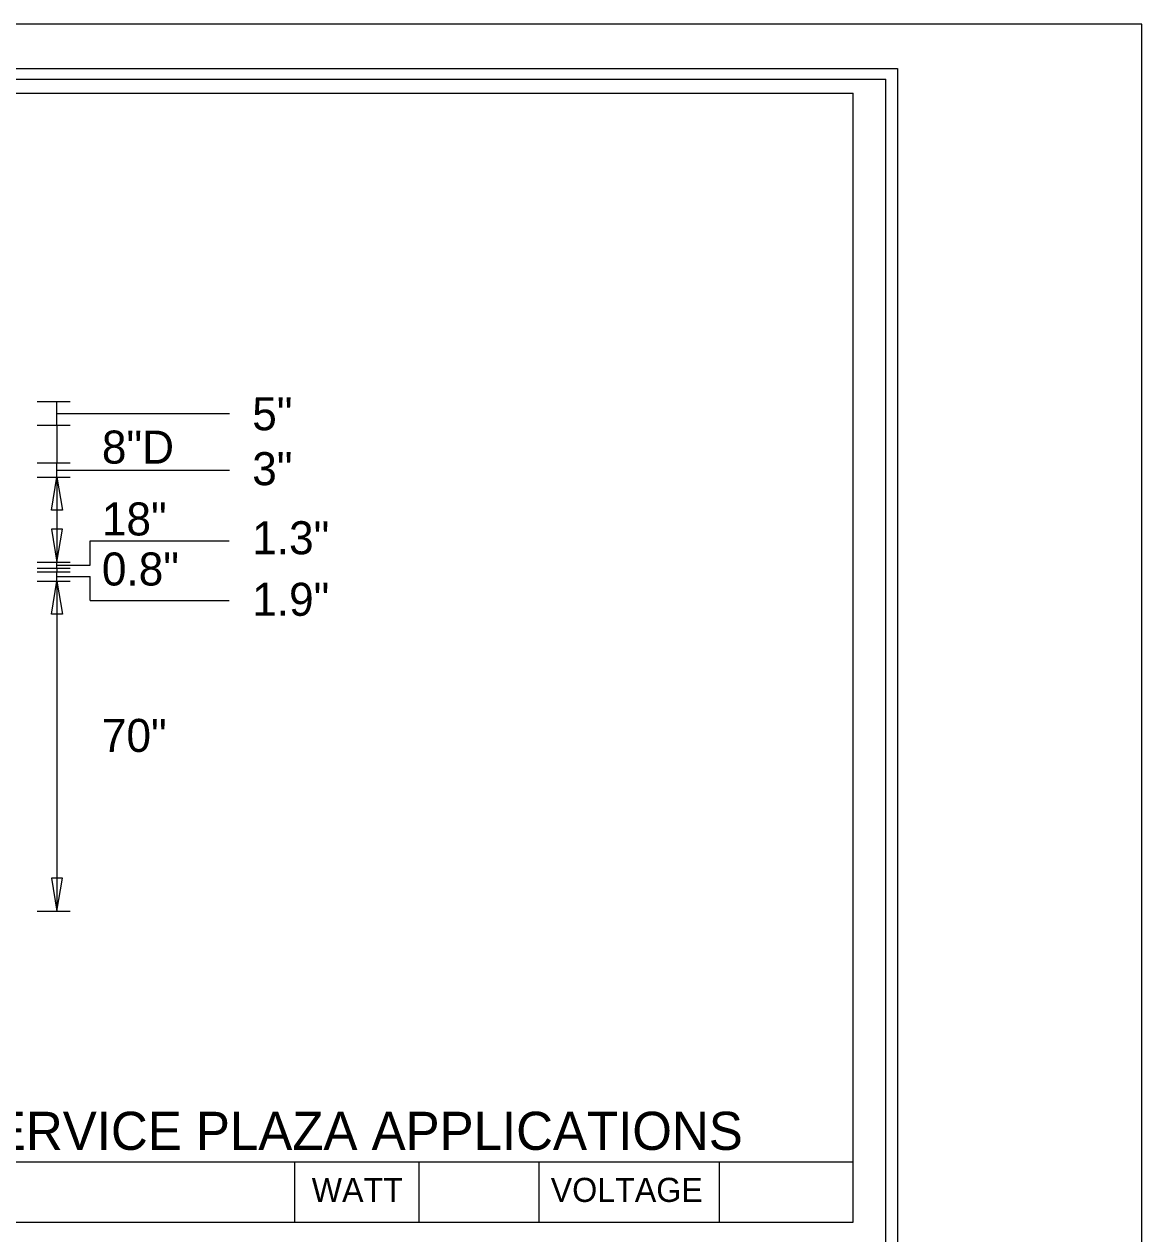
# Model space of a CAD drawing. Extents: x 17890628 to 17891459, y 17897314 to 17897992.
# Drawn here: x 17890811.01 to 17890830.75, y 17897475.46 to 17897496.82 of the extents above; entities that cross this region are included whole.
import ezdxf

# ---------------------------------------------------------------- set-up
doc = ezdxf.new("R2010")
doc.units = 0
for name, color, linetype in [('GSDims', 7, 'Continuous'), ('PlotBorder_dp', 7, 'Continuous'), ('SheetBorder_dp', 7, 'Continuous'), ('SheetLinesMisc2_dp', 7, 'Continuous'), ('TextMinor', 7, 'Continuous')]:
    doc.layers.add(name, color=color, linetype=linetype)

msp = doc.modelspace()

# ---------------------------------------------------------------- linework, layer by layer
at = {"layer": 'GSDims'}
for p, q in [((17890811.238, 17897490.153), (17890811.821, 17897490.153)), ((17890811.588, 17897489.736), (17890811.588, 17897490.153)), ((17890811.588, 17897489.945), (17890814.634, 17897489.945)), ((17890811.238, 17897489.736), (17890811.821, 17897489.736)), ((17890811.238, 17897489.736), (17890811.821, 17897489.736)), ((17890811.588, 17897489.736), (17890811.588, 17897489.07)), ((17890811.238, 17897489.07), (17890811.821, 17897489.07)), ((17890811.238, 17897489.07), (17890811.821, 17897489.07)), ((17890811.588, 17897488.82), (17890811.588, 17897489.07)), ((17890811.238, 17897488.82), (17890811.821, 17897488.82)), ((17890811.238, 17897488.82), (17890811.821, 17897488.82)), ((17890811.588, 17897488.945), (17890814.634, 17897488.945)), ((17890811.588, 17897488.82), (17890811.588, 17897487.32)), ((17890812.176, 17897487.264), (17890812.176, 17897487.692)), ((17890812.176, 17897487.692), (17890814.626, 17897487.692)), ((17890811.238, 17897487.32), (17890811.821, 17897487.32)), ((17890811.238, 17897487.32), (17890811.821, 17897487.32)), ((17890811.588, 17897487.209), (17890811.588, 17897487.32)), ((17890811.238, 17897487.209), (17890811.821, 17897487.209)), ((17890811.238, 17897487.209), (17890811.821, 17897487.209)), ((17890811.238, 17897487.146), (17890811.821, 17897487.146)), ((17890811.238, 17897487.146), (17890811.821, 17897487.146)), ((17890811.588, 17897487.264), (17890812.176, 17897487.264)), ((17890811.588, 17897487.209), (17890811.588, 17897487.146)), ((17890811.588, 17897486.984), (17890811.588, 17897487.146)), ((17890811.238, 17897486.984), (17890811.821, 17897486.984)), ((17890811.238, 17897486.984), (17890811.821, 17897486.984)), ((17890811.588, 17897487.065), (17890812.176, 17897487.065)), ((17890811.588, 17897486.984), (17890811.588, 17897481.153)), ((17890812.176, 17897486.638), (17890812.176, 17897487.065)), ((17890812.176, 17897486.638), (17890814.626, 17897486.638)), ((17890811.238, 17897481.153), (17890811.821, 17897481.153))]:
    msp.add_line(p, q, dxfattribs=at)
for points in [[(17890811.588, 17897488.82), (17890811.685, 17897488.236), (17890811.49, 17897488.236)], [(17890811.588, 17897487.32), (17890811.685, 17897487.903), (17890811.49, 17897487.903)], [(17890811.588, 17897486.984), (17890811.685, 17897486.401), (17890811.49, 17897486.401)], [(17890811.588, 17897481.153), (17890811.685, 17897481.736), (17890811.49, 17897481.736)]]:
    msp.add_lwpolyline(points, close=True, dxfattribs=at)
at = {"layer": 'PlotBorder_dp'}
msp.add_lwpolyline([(17890701.346, 17897413.687), (17890830.745, 17897413.687), (17890830.745, 17897496.818), (17890701.346, 17897496.818)], close=True, dxfattribs=at)
at = {"layer": 'SheetBorder_dp'}
for p, q in [((17890705.659, 17897496.034), (17890826.432, 17897496.034)), ((17890826.432, 17897496.034), (17890826.432, 17897414.472))]:
    msp.add_line(p, q, dxfattribs=at)
at = {"layer": 'SheetLinesMisc2_dp'}
for p, q in [((17890705.872, 17897495.849), (17890826.223, 17897495.849)), ((17890826.223, 17897420.931), (17890826.223, 17897495.848)), ((17890784.715, 17897495.599), (17890825.647, 17897495.599)), ((17890825.647, 17897475.661), (17890825.647, 17897495.599)), ((17890784.715, 17897476.729), (17890825.647, 17897476.729)), ((17890815.782, 17897476.729), (17890815.782, 17897475.661)), ((17890817.978, 17897476.729), (17890817.978, 17897475.661)), ((17890820.095, 17897476.729), (17890820.095, 17897475.661)), ((17890823.283, 17897476.729), (17890823.283, 17897475.661)), ((17890784.715, 17897475.661), (17890825.647, 17897475.661))]:
    msp.add_line(p, q, dxfattribs=at)

# ---------------------------------------------------------------- texts
at = {"layer": 'GSDims'}
for s, height, p in [('5"', 0.5833, (17890815.036, 17897489.647)), ('8"D', 0.5833, (17890812.381, 17897489.058)), ('3"', 0.5833, (17890815.036, 17897488.677)), ('18"', 0.5833, (17890812.381, 17897487.789)), ('1.3"', 0.5833, (17890815.036, 17897487.457)), ('0.8"', 0.5833, (17890812.381, 17897486.905)), ('1.9"', 0.5833, (17890815.036, 17897486.37)), ('70"', 0.5833, (17890812.381, 17897483.966)), ('SERVICE PLAZA APPLICATIONS', 0.67331, (17890809.839, 17897476.938))]:
    msp.add_text(s, height=height, dxfattribs=at).set_placement(p)
at = {"layer": 'TextMinor'}
for s, p in [('WATT', (17890816.086, 17897476.019)), ('VOLTAGE', (17890820.307, 17897476.019))]:
    msp.add_text(s, height=0.4252, dxfattribs=at).set_placement(p)

doc.saveas('drawing.dxf')
